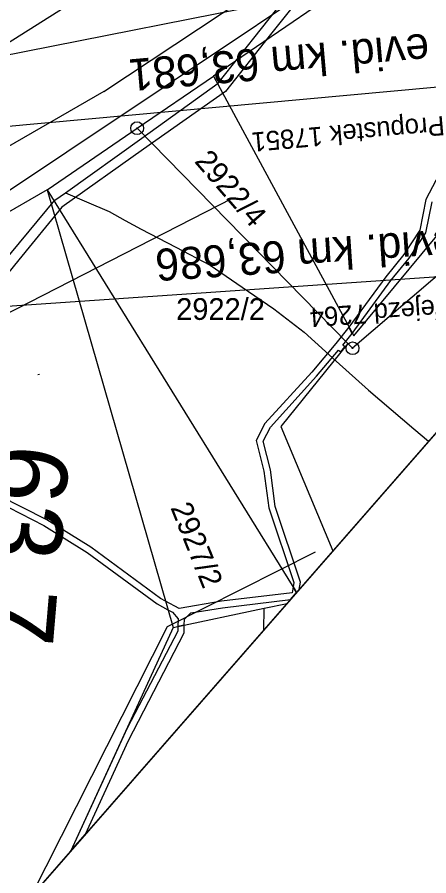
# Model space of a CAD drawing. Extents: x -620475 to -619963, y -1123010 to -1122510.
# Drawn here: x -620107.7 to -620075.4, y -1122949.2 to -1122882 of the extents above; entities that cross this region are included whole.
import ezdxf

# ---------------------------------------------------------------- set-up
doc = ezdxf.new("R2010")
doc.units = 0
for name, color, linetype in [('bubliny', 7, 'Continuous'), ('CETIN', 7, 'Continuous'), ('Hranice parcel', 7, 'Continuous'), ('Parcelní čísla', 7, 'Continuous'), ('Rámečky', 7, 'Continuous'), ('Rámečky-tisk', 7, 'Continuous'), ('VAS vodovod', 7, 'Continuous'), ('Vnitřní kresba', 7, 'Continuous'), ('Vrstva 19', 7, 'Continuous'), ('Vrstva 4', 7, 'Continuous'), ('Vrstva 7', 7, 'Continuous'), ('Věcná břemena k části', 7, 'Continuous'), ('Značky bodu BP', 7, 'Continuous'), ('ČD-T OSS Ždár', 7, 'Continuous')]:
    doc.layers.add(name, color=color, linetype=linetype)

msp = doc.modelspace()

# ---------------------------------------------------------------- linework, layer by layer
at = {"layer": 'bubliny'}
msp.add_line((-620129.216, -1122889.068), (-620082.81, -1122879.869), dxfattribs=at)
at = {"layer": 'CETIN'}
for points in [[(-620127.251, -1122919.476), (-620126.15, -1122907.427), (-620051.64, -1122857.73)], [(-620084.31, -1122923.86), (-620095.91, -1122929.69), (-620106.592, -1122950.812)]]:
    msp.add_lwpolyline(points, dxfattribs=at)
at = {"layer": 'Hranice parcel'}
for p, q in [((-620081.71, -1122879.39), (-620092.29, -1122886.6)), ((-620098.27, -1122890.68), (-620092.29, -1122886.6)), ((-620105.32, -1122895.5), (-620098.27, -1122890.68)), ((-620081.76, -1122907.52), (-620098.27, -1122890.68)), ((-620105.32, -1122895.5), (-620127.22, -1122908.12)), ((-620105.32, -1122895.5), (-620085.779, -1122927.019)), ((-620105.32, -1122895.5), (-620095.45, -1122929.76)), ((-620088.31, -1122928.24), (-620086.519, -1122927.865)), ((-620095.45, -1122929.76), (-620088.31, -1122928.24))]:
    msp.add_line(p, q, dxfattribs=at)
for points in [[(-620092.29, -1122886.6), (-620081.3, -1122906.94), (-620073.77, -1122897.87), (-620073.48, -1122898.22), (-620072.03, -1122899.92)], [(-620072.03, -1122899.92), (-620081.39, -1122907.9), (-620081.76, -1122907.52)], [(-620081.76, -1122907.52), (-620087, -1122914.03), (-620082.926, -1122923.757)], [(-620088.352, -1122929.961), (-620088.31, -1122928.24)], [(-620095.45, -1122929.76), (-620103.459, -1122947.23)]]:
    msp.add_lwpolyline(points, dxfattribs=at)
at = {"layer": 'Rámečky'}
msp.add_line((-620158.492, -1123010.143), (-619962.948, -1122786.6), dxfattribs=at)
at = {"layer": 'Rámečky-tisk'}
msp.add_lwpolyline([(-620158.492, -1123010.143), (-619962.948, -1122786.6), (-620279.069, -1122510.073)], dxfattribs=at)
at = {"layer": 'VAS vodovod'}
msp.add_line((-620106.043, -1122909.957), (-620105.934, -1122909.933), dxfattribs=at)
for points in [[(-620142.983, -1122992.414), (-620138.823, -1122978.35), (-620134.021, -1122962.118), (-620127.905, -1122941.449), (-620121.79, -1122920.781), (-620120.515, -1122917.151), (-620119.24, -1122913.52), (-620115.38, -1122908.995), (-620111.52, -1122904.47), (-620108.12, -1122900.395), (-620104.72, -1122896.32), (-620104.308, -1122896.031), (-620103.896, -1122895.74), (-620097.905, -1122891.451), (-620091.914, -1122887.161), (-620088.517, -1122882.866), (-620085.12, -1122878.57), (-620078.301, -1122874.062), (-620071.488, -1122869.557), (-620071.483, -1122869.553), (-620060.436, -1122861.917), (-620049.39, -1122854.28), (-620049.25, -1122854.183), (-620049.11, -1122854.085)], [(-620066.7, -1122866.755), (-620084.48, -1122879.15), (-620087.916, -1122883.483), (-620091.352, -1122887.816), (-620097.766, -1122892.333), (-620104.18, -1122896.85), (-620107.54, -1122900.975), (-620110.9, -1122905.1), (-620114.72, -1122909.545), (-620118.54, -1122913.991), (-620119.85, -1122917.545), (-620121.16, -1122921.1), (-620132.06, -1122957.94), (-620141.89, -1122991.164)], [(-620103.881, -1122895.73), (-620102.24, -1122896.44), (-620100.46, -1122897.21), (-620099.21, -1122897.89), (-620097.96, -1122898.57), (-620095.25, -1122899.99), (-620092.54, -1122901.41), (-620090.05, -1122903.115), (-620087.56, -1122904.82), (-620085.18, -1122906.65), (-620082.665, -1122908.915), (-620080.15, -1122911.18), (-620076.588, -1122914.199), (-620075.426, -1122915.183)]]:
    msp.add_lwpolyline(points, dxfattribs=at)
at = {"layer": 'Vnitřní kresba'}
for p, q in [((-620080.37, -1122866.39), (-620119.37, -1122890.92)), ((-620100.87, -1122887.82), (-620079.86, -1122873.87)), ((-620100.87, -1122887.82), (-620115.07, -1122895.95))]:
    msp.add_line(p, q, dxfattribs=at)
at = {"layer": 'Vrstva 19'}
msp.add_line((-620074.697, -1122887.466), (-620134.446, -1122892.947), dxfattribs=at)
at = {"layer": 'Vrstva 4'}
msp.add_line((-620133.061, -1122906.266), (-620073.199, -1122902.2), dxfattribs=at)
at = {"layer": 'Věcná břemena k části'}
for p, q in [((-620086.26, -1122927.569), (-620085.778, -1122927.018)), ((-620085.778, -1122927.018), (-620085.569, -1122926.779)), ((-620103.461, -1122947.232), (-620102.31, -1122945.916))]:
    msp.add_line(p, q, dxfattribs=at)
for points in [[(-620072.53, -1122890.37), (-620075.64, -1122896.27), (-620076.12, -1122898.67), (-620077.36, -1122900.56), (-620078.79, -1122902.31), (-620081.67, -1122906.26), (-620081.41, -1122906.74), (-620078.39, -1122902.61), (-620076.96, -1122900.86), (-620075.64, -1122898.87), (-620075.16, -1122896.43)], [(-620085.569, -1122926.779), (-620085.48, -1122926.2), (-620087.45, -1122920.28), (-620087.83, -1122917.42), (-620088.4, -1122915.17), (-620087.83, -1122914.07), (-620084.21, -1122910.09), (-620082.48, -1122908.04), (-620082.3, -1122908.18), (-620081.99, -1122907.79), (-620082.16, -1122907.66), (-620081.41, -1122906.74), (-620081.67, -1122906.26), (-620082.7, -1122907.53), (-620084.59, -1122909.76), (-620088.25, -1122913.79), (-620088.93, -1122915.11), (-620088.33, -1122917.52), (-620087.94, -1122920.4), (-620086, -1122926.24), (-620086.05, -1122926.58), (-620085.778, -1122927.018)], [(-620085.778, -1122927.018), (-620086.05, -1122926.58), (-620086.12, -1122927.04), (-620091.66, -1122927.7), (-620094.97, -1122928.27), (-620096.05, -1122927.68), (-620096.44, -1122927.47), (-620101.9, -1122923.47), (-620105.34, -1122921.32), (-620109.13, -1122919.41)], [(-620109.27, -1122919.9), (-620105.58, -1122921.76), (-620102.18, -1122923.89), (-620096.7, -1122927.89), (-620095.86, -1122928.36), (-620095.5, -1122928.55), (-620095.06, -1122929.07), (-620095.08, -1122929.68), (-620094.58, -1122929.57), (-620094.56, -1122929.09), (-620094.05, -1122928.61), (-620091.58, -1122928.2), (-620086.26, -1122927.569)], [(-620102.31, -1122945.916), (-620098.95, -1122938.59), (-620094.59, -1122930.17), (-620094.58, -1122929.57), (-620095.08, -1122929.68), (-620095.09, -1122930.04), (-620099.06, -1122937.63), (-620103.461, -1122947.232)]]:
    msp.add_lwpolyline(points, dxfattribs=at)
at = {"layer": 'Značky bodu BP'}
for centre, radius in [((-620098.27, -1122890.68), 0.5), ((-620098.27, -1122890.68), 0.0303), ((-620081.39, -1122907.9), 0.5), ((-620081.39, -1122907.9), 0.0303)]:
    msp.add_circle(centre, radius, dxfattribs=at)
at = {"layer": 'ČD-T OSS Ždár'}
msp.add_lwpolyline([(-620090.831, -1122896.183), (-620117.323, -1122909.731), (-620123.829, -1122913.059), (-620127.58, -1122923.445), (-620145.628, -1122923.723), (-620198.095, -1122954.464)], dxfattribs=at)

# ---------------------------------------------------------------- texts
at = {"layer": 'Parcelní čísla'}
for s, rotation, p in [('2922/4', 311, (-620093.837, -1122893.304)), ('2927/2', 292, (-620095.681, -1122920.365))]:
    msp.add_text(s, height=1.7, rotation=rotation, dxfattribs=at).set_placement(p)
msp.add_text('2922/2', height=1.7, dxfattribs=at).set_placement((-620095.21, -1122905.68))
at = {"layer": 'Vrstva 19'}
for s, height, p in [('evid. km 63,681', 2.5, (-620075.491, -1122883.258)), ('Propustek 17851', 1.5, (-620074.238, -1122889.718))]:
    msp.add_text(s, height=height, rotation=184.97997, dxfattribs=at).set_placement(p)
at = {"layer": 'Vrstva 4'}
for s, height, p in [('evid. km 63,686', 2.5, (-620073.369, -1122898.557)), ('Přejezd 7264', 1.5, (-620072.983, -1122903.954))]:
    msp.add_text(s, height=height, rotation=183.8855, dxfattribs=at).set_placement(p)
at = {"layer": 'Vrstva 7'}
msp.add_text('63,7', height=6, rotation=265.12133, dxfattribs=at).set_placement((-620109.539, -1122915.266))

doc.saveas('drawing.dxf')
